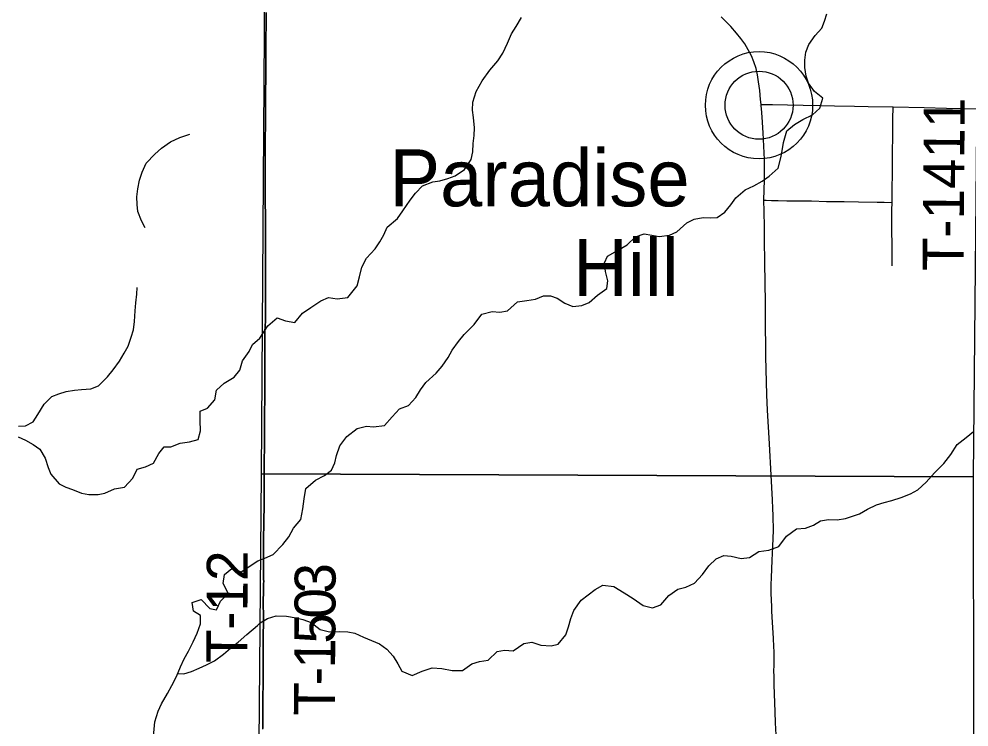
# Model space of a CAD drawing. Extents: x 0 to 70.2, y 0 to 31.4.
# Drawn here: x 6.434 to 7.753, y 14.97 to 15.952 of the extents above; entities that cross this region are included whole.
import ezdxf

# ---------------------------------------------------------------- set-up
doc = ezdxf.new("R2010")
doc.units = 0
for name, color, linetype in [('GM_X_County_Road', 7, 'Continuous'), ('GM_X_Minor_River', 7, 'Continuous'), ('GM_X_Section', 7, 'Continuous'), ('GM_X_Section_Text', 7, 'Continuous'), ('GM_X_State_Route', 7, 'Continuous'), ('GM_X_Township_Road', 7, 'Continuous'), ('GM_X_Township_Road_Text', 7, 'Continuous'), ('GM_X_Unincorporated', 7, 'Continuous'), ('GM_X_Unincorporated_Location', 7, 'Continuous'), ('GM_X_Unincorporated_Text', 7, 'Continuous'), ('SH_Cut_Line', 7, 'Continuous')]:
    doc.layers.add(name, color=color, linetype=linetype)

msp = doc.modelspace()

# ---------------------------------------------------------------- linework, layer by layer
at = {"layer": 'GM_X_County_Road'}
for points in [[(7.4642, 15.8337), (7.4797, 15.8335), (7.5009, 15.8332), (7.5227, 15.8328), (7.546, 15.8323), (7.5661, 15.8319), (7.5939, 15.8312), (7.6127, 15.8309), (7.6473, 15.8303)], [(7.6473, 15.8303), (7.6903, 15.8292), (7.7214, 15.8286), (7.7679, 15.8277), (7.8052, 15.8268), (7.917, 15.8247), (7.9789, 15.8235), (8.041, 15.8223), (8.0691, 15.822), (8.1468, 15.8216), (8.1996, 15.8212), (8.2617, 15.8195), (8.2673, 15.8194)]]:
    msp.add_lwpolyline(points, dxfattribs=at)
at = {"layer": 'GM_X_Minor_River'}
for points in [[(6.7657, 15.2005), (6.7754, 15.2041), (6.787, 15.2093), (6.8003, 15.2233), (6.8084, 15.2337), (6.8153, 15.2456), (6.8253, 15.258), (6.828, 15.2725), (6.8299, 15.2866), (6.8322, 15.301), (6.8456, 15.3124), (6.858, 15.3187), (6.8677, 15.3262), (6.8723, 15.3365), (6.8748, 15.3465), (6.8794, 15.3598), (6.8893, 15.373), (6.9035, 15.3839), (6.9166, 15.3873), (6.9261, 15.3864), (6.9412, 15.3883), (6.952, 15.4003), (6.9623, 15.4115), (6.9747, 15.416), (6.9847, 15.4272), (6.9912, 15.4376), (6.9986, 15.4481), (7.0131, 15.4609), (7.0212, 15.4706), (7.0296, 15.4826), (7.0351, 15.4926), (7.0439, 15.5049), (7.052, 15.5146), (7.0657, 15.5282), (7.0767, 15.5425), (7.0906, 15.5466), (7.1013, 15.5454), (7.1122, 15.5475), (7.126, 15.5596), (7.1388, 15.5618), (7.1509, 15.5636), (7.1621, 15.5681), (7.1716, 15.5679), (7.1812, 15.5651), (7.1919, 15.5578), (7.2027, 15.5531), (7.2155, 15.5545), (7.2253, 15.5589), (7.2368, 15.5691), (7.2502, 15.5781), (7.2515, 15.5888), (7.2481, 15.602), (7.2467, 15.6137), (7.251, 15.6233), (7.2649, 15.6312), (7.278, 15.6391), (7.2898, 15.65), (7.3019, 15.6541), (7.3125, 15.6521), (7.3224, 15.6504), (7.3371, 15.6523), (7.3473, 15.6571), (7.361, 15.6692), (7.3711, 15.6747), (7.3839, 15.6766), (7.3934, 15.6764), (7.4033, 15.6766), (7.4137, 15.6841), (7.4222, 15.6942), (7.4291, 15.7042), (7.4421, 15.7151), (7.4541, 15.7207), (7.4657, 15.7271), (7.4754, 15.7341), (7.488, 15.7454), (7.4915, 15.7596), (7.4932, 15.7691), (7.4952, 15.7809), (7.4997, 15.7969), (7.5105, 15.8059), (7.5221, 15.8127), (7.5356, 15.8194), (7.5456, 15.8284), (7.5498, 15.8425), (7.5383, 15.8517), (7.53, 15.8633), (7.5268, 15.8731), (7.525, 15.8848), (7.5247, 15.8951), (7.5264, 15.9061), (7.5303, 15.9168), (7.5391, 15.9292), (7.5483, 15.9393), (7.5523, 15.9492), (7.5551, 15.9595)], [(6.7682, 15.5096), (6.7793, 15.5263), (6.7923, 15.5376), (6.8041, 15.5334), (6.8171, 15.531), (6.8277, 15.5442), (6.8393, 15.552), (6.8531, 15.5611), (6.8636, 15.5659), (6.8758, 15.5639), (6.8905, 15.5658), (6.9034, 15.582), (6.9065, 15.5946), (6.91, 15.608), (6.9162, 15.6203), (6.9283, 15.6335), (6.9349, 15.6431), (6.9404, 15.6527), (6.9451, 15.6635), (6.9596, 15.6756), (6.9669, 15.686), (6.9768, 15.7007), (6.9842, 15.7107), (6.9941, 15.7208), (7.0084, 15.7261), (7.0182, 15.7278), (7.0295, 15.7307), (7.0393, 15.7348), (7.0524, 15.7434), (7.0615, 15.7573), (7.0639, 15.768), (7.0644, 15.7794), (7.066, 15.7904), (7.0665, 15.8011), (7.0647, 15.8155), (7.0637, 15.8257), (7.0642, 15.8367), (7.0688, 15.8516), (7.0768, 15.8666), (7.0878, 15.8813), (7.0985, 15.894), (7.1058, 15.9048), (7.1123, 15.9187), (7.1177, 15.9317), (7.1239, 15.9417), (7.1316, 15.9544)], [(6.6092, 15.6625), (6.6039, 15.6723), (6.599, 15.6852), (6.5982, 15.6947), (6.5978, 15.7053), (6.599, 15.7167), (6.6013, 15.7285), (6.6051, 15.7395), (6.6108, 15.752), (6.6225, 15.7645), (6.632, 15.7732), (6.6445, 15.782), (6.6574, 15.788), (6.6711, 15.7922)], [(6.4332, 15.3875), (6.443, 15.3878), (6.4536, 15.3935), (6.4601, 15.4034), (6.4688, 15.4178), (6.4798, 15.4284), (6.4893, 15.4322), (6.4995, 15.4353), (6.5113, 15.4372), (6.5207, 15.4383), (6.534, 15.4391), (6.5443, 15.4432), (6.5568, 15.4557), (6.5647, 15.4656), (6.5735, 15.4777), (6.5799, 15.4884), (6.5856, 15.4982), (6.5898, 15.5107), (6.5928, 15.521), (6.5943, 15.5327), (6.5955, 15.5472), (6.5963, 15.5582), (6.5974, 15.5703), (6.5982, 15.5798)], [(6.4331, 15.3723), (6.443, 15.3681), (6.4536, 15.362), (6.4631, 15.3556), (6.4703, 15.3431), (6.4744, 15.3302), (6.4782, 15.3207), (6.4896, 15.3074), (6.4991, 15.3025), (6.5085, 15.2995), (6.5207, 15.2945), (6.5309, 15.2926), (6.5438, 15.2926), (6.5533, 15.2945), (6.5665, 15.3002), (6.5806, 15.3025), (6.5923, 15.315), (6.598, 15.3275), (6.6098, 15.331), (6.6208, 15.3359), (6.628, 15.3492), (6.6356, 15.3587), (6.645, 15.3587), (6.6579, 15.3636), (6.6708, 15.3655), (6.6826, 15.3689), (6.686, 15.3807), (6.6856, 15.3951), (6.6853, 15.408), (6.6955, 15.4125), (6.7061, 15.4239), (6.708, 15.4372), (6.719, 15.447), (6.7327, 15.4554), (6.7406, 15.4652), (6.7444, 15.4781), (6.7535, 15.4907), (6.7581, 15.5005), (6.7682, 15.5096)], [(6.765, 15.1106), (6.7687, 15.1147), (6.7792, 15.1203), (6.7909, 15.124), (6.8053, 15.1236), (6.8186, 15.1216), (6.8281, 15.1192), (6.8396, 15.1149), (6.8523, 15.1053), (6.8649, 15.1018), (6.8789, 15.1025), (6.8903, 15.1021), (6.9002, 15.1), (6.9124, 15.0946), (6.9235, 15.0899), (6.9346, 15.0853), (6.9447, 15.0779), (6.9536, 15.0683), (6.9599, 15.0578), (6.9655, 15.0473), (6.9796, 15.0416), (6.9935, 15.0472), (7.0074, 15.0521), (7.0211, 15.0513), (7.0355, 15.0482), (7.0495, 15.0485), (7.0626, 15.0576), (7.0731, 15.0609), (7.0852, 15.0627), (7.0978, 15.0747), (7.108, 15.0765), (7.1201, 15.0756), (7.1347, 15.0859), (7.146, 15.0876), (7.1582, 15.0834), (7.1727, 15.0826), (7.1824, 15.0851), (7.1931, 15.0979), (7.1967, 15.109), (7.2002, 15.1204), (7.2041, 15.1315), (7.2144, 15.1458), (7.2337, 15.1607), (7.2442, 15.1666), (7.2598, 15.1651), (7.274, 15.156), (7.2867, 15.1483), (7.3002, 15.1384), (7.3135, 15.1353), (7.3248, 15.1393), (7.3362, 15.1525), (7.3485, 15.1611), (7.3598, 15.1641), (7.3718, 15.1697), (7.3829, 15.1813), (7.3914, 15.1937), (7.4017, 15.2034), (7.4122, 15.2078), (7.4225, 15.2069), (7.4366, 15.2035), (7.4479, 15.2052), (7.461, 15.2135), (7.4746, 15.2154), (7.4885, 15.2202), (7.4992, 15.2345), (7.5133, 15.2447), (7.5258, 15.2458), (7.5367, 15.2499), (7.5464, 15.2558), (7.5577, 15.2576), (7.5695, 15.2575), (7.5812, 15.2593), (7.6007, 15.2658), (7.6116, 15.2721), (7.6243, 15.2781), (7.6349, 15.2814), (7.6454, 15.2843), (7.6586, 15.2884), (7.6713, 15.2933), (7.6814, 15.2992), (7.6933, 15.3097), (7.7048, 15.3225), (7.7177, 15.3354), (7.7276, 15.3481), (7.7364, 15.362), (7.7487, 15.3718), (7.7587, 15.38)], [(6.6206, 14.957), (6.6225, 14.9771), (6.6274, 14.9919), (6.632, 15.0021), (6.6403, 15.0165), (6.6464, 15.0275), (6.6525, 15.04), (6.6582, 15.0533), (6.6635, 15.0643), (6.6695, 15.0753), (6.6756, 15.0882), (6.6813, 15.1), (6.6859, 15.1129), (6.6862, 15.1246), (6.6764, 15.1307), (6.6745, 15.1428), (6.687, 15.147), (6.6988, 15.1345), (6.7082, 15.1326), (6.7139, 15.1447), (6.7242, 15.1557), (6.7173, 15.169), (6.7193, 15.1815), (6.7295, 15.1899), (6.7424, 15.1853), (6.7657, 15.2005)], [(6.6543, 15.0443), (6.6627, 15.0435), (6.6737, 15.0469), (6.6843, 15.0518), (6.6945, 15.0564), (6.7052, 15.0617), (6.7181, 15.0712), (6.7275, 15.0795), (6.7382, 15.0878), (6.7503, 15.0981), (6.765, 15.1106)]]:
    msp.add_lwpolyline(points, dxfattribs=at)
at = {"layer": 'GM_X_Section'}
for points in [[(6.7778, 16.3386), (7.7683, 16.3298), (7.7584, 15.3168), (6.7706, 15.321)], [(6.7706, 15.321), (7.7584, 15.3168), (7.7596, 14.2988), (6.7617, 14.3072)]]:
    msp.add_lwpolyline(points, close=True, dxfattribs=at)
at = {"layer": 'GM_X_Section_Text'}
for points in [[(6.7771, 15.9614), (6.7769, 15.9086), (6.7768, 15.8931), (6.7765, 15.8683), (6.7763, 15.8528), (6.7762, 15.8188), (6.7758, 15.7723), (6.7757, 15.7506), (6.7759, 15.7165), (6.7761, 15.6606), (6.776, 15.6419), (6.7762, 15.5829), (6.7763, 15.5707), (6.7763, 15.5487), (6.7761, 15.5336), (6.7755, 15.5187), (6.7754, 15.5055), (6.7754, 15.4901), (6.7752, 15.4713), (6.7753, 15.4495), (6.7752, 15.4247), (6.7749, 15.4062), (6.7746, 15.3596), (6.7745, 15.3381), (6.7743, 15.3099), (6.7742, 15.2818), (6.7737, 15.2508), (6.7735, 15.2322), (6.7735, 15.226), (6.7736, 15.2198), (6.7736, 15.1998), (6.7736, 15.1926), (6.7736, 15.1834), (6.7736, 15.1793), (6.7736, 15.1751), (6.7737, 15.1719), (6.7736, 15.169), (6.7735, 15.1661), (6.7733, 15.1573), (6.7731, 15.145), (6.7734, 15.12), (6.7732, 15.092), (6.773, 15.0547), (6.7728, 15.0329), (6.7726, 15.0081), (6.7725, 14.9863), (6.7723, 14.9677)], [(6.7723, 14.9677), (6.7725, 14.9863), (6.7726, 15.0081), (6.7728, 15.0329), (6.773, 15.0547), (6.7732, 15.092), (6.7734, 15.12), (6.7731, 15.145), (6.7733, 15.1573), (6.7735, 15.1661), (6.7736, 15.169), (6.7737, 15.1719), (6.7736, 15.1751), (6.7736, 15.1793), (6.7736, 15.1834), (6.7736, 15.1926), (6.7736, 15.1998), (6.7736, 15.2198), (6.7735, 15.226), (6.7735, 15.2322), (6.7737, 15.2508), (6.7742, 15.2818), (6.7743, 15.3099), (6.7745, 15.3381), (6.7746, 15.3596), (6.7749, 15.4062), (6.7752, 15.4247), (6.7753, 15.4495), (6.7752, 15.4713), (6.7754, 15.4901), (6.7754, 15.5055), (6.7755, 15.5187), (6.7761, 15.5336), (6.7763, 15.5487), (6.7763, 15.5707), (6.7762, 15.5829), (6.776, 15.6419), (6.7761, 15.6606), (6.7759, 15.7165), (6.7757, 15.7506), (6.7758, 15.7723), (6.7762, 15.8188), (6.7763, 15.8528), (6.7765, 15.8683), (6.7768, 15.8931), (6.7769, 15.9086), (6.7771, 15.9614)]]:
    msp.add_lwpolyline(points, dxfattribs=at)
at = {"layer": 'GM_X_State_Route'}
msp.add_lwpolyline([(7.4856, 14.9508), (7.4841, 14.9756), (7.4834, 14.9911), (7.4823, 15.0284), (7.482, 15.0408), (7.4819, 15.047), (7.4821, 15.0562), (7.4822, 15.0593), (7.4823, 15.0624), (7.4821, 15.0748), (7.4818, 15.081), (7.4814, 15.0934), (7.48, 15.1151), (7.4792, 15.1306), (7.4788, 15.1399), (7.4787, 15.143), (7.4781, 15.1584), (7.4782, 15.1675), (7.4784, 15.1767), (7.4796, 15.2015), (7.4805, 15.2201), (7.481, 15.2325), (7.4811, 15.2419), (7.4808, 15.2636), (7.4805, 15.2729), (7.4801, 15.2853), (7.4781, 15.3194), (7.4758, 15.3628), (7.4732, 15.4093), (7.4721, 15.431), (7.4708, 15.4838), (7.4701, 15.5397), (7.47, 15.5584), (7.4691, 15.6143), (7.469, 15.6458), (7.4686, 15.6638), (7.4685, 15.6853), (7.4681, 15.7007), (7.4687, 15.729), (7.4689, 15.7415), (7.4687, 15.7571), (7.4681, 15.7757), (7.4671, 15.7942), (7.4657, 15.8159), (7.4647, 15.8282), (7.4644, 15.8313), (7.4642, 15.8337), (7.4634, 15.8405), (7.4622, 15.8528), (7.4607, 15.8652), (7.4592, 15.8745), (7.4571, 15.8836), (7.4542, 15.8926), (7.4506, 15.9012), (7.4463, 15.9096), (7.4414, 15.9176), (7.436, 15.9253), (7.4301, 15.9326), (7.4219, 15.9419), (7.4088, 15.9553)], dxfattribs=at)
at = {"layer": 'GM_X_Township_Road'}
for points in [[(6.7725, 14.9671), (6.7727, 14.9858), (6.7728, 15.0075), (6.773, 15.0324), (6.7732, 15.0541), (6.7734, 15.0915), (6.7736, 15.1194), (6.7734, 15.1445), (6.7735, 15.1567), (6.7737, 15.1656), (6.7738, 15.1684), (6.7739, 15.1714), (6.7739, 15.1745), (6.7739, 15.1788), (6.7739, 15.1828), (6.7738, 15.1921), (6.7738, 15.1993), (6.7738, 15.2192), (6.7737, 15.2254), (6.7737, 15.2316), (6.7739, 15.2502), (6.7744, 15.2813), (6.7745, 15.3094), (6.7747, 15.3376), (6.7748, 15.3591), (6.7751, 15.4057), (6.7754, 15.4241), (6.7755, 15.449), (6.7755, 15.4707), (6.7756, 15.4895), (6.7756, 15.5049), (6.7757, 15.5182), (6.7763, 15.533), (6.7766, 15.5482), (6.7766, 15.5702), (6.7764, 15.5824), (6.7762, 15.6414), (6.7764, 15.66), (6.7761, 15.7159), (6.7759, 15.7501), (6.776, 15.7718), (6.7764, 15.8182), (6.7765, 15.8522), (6.7767, 15.8677), (6.7771, 15.8925), (6.7771, 15.9081), (6.7773, 15.9609)], [(7.6459, 15.6977), (7.6461, 15.7044), (7.6461, 15.7133), (7.6463, 15.7409), (7.6466, 15.7691), (7.6467, 15.7879), (7.6468, 15.8004), (7.6471, 15.816), (7.6473, 15.8276), (7.6473, 15.8303)], [(7.4681, 15.7007), (7.4713, 15.7007), (7.4786, 15.7006), (7.4879, 15.7006), (7.5, 15.7001), (7.5187, 15.6998), (7.5341, 15.6997), (7.5548, 15.6992), (7.5794, 15.6988), (7.5994, 15.6985), (7.6254, 15.6982), (7.6351, 15.6979), (7.6459, 15.6977)], [(7.6462, 15.6096), (7.6459, 15.6378), (7.6456, 15.6597), (7.6455, 15.6722), (7.6457, 15.687), (7.6459, 15.6977)]]:
    msp.add_lwpolyline(points, dxfattribs=at)
at = {"layer": 'GM_X_Unincorporated'}
for radius in [0.0744, 0.0472]:
    msp.add_circle((7.4612, 15.8326), radius, dxfattribs=at)
at = {"layer": 'GM_X_Unincorporated_Location'}
msp.add_line((7.4612, 15.8326), (7.4612, 15.8326), dxfattribs=at)
at = {"layer": 'SH_Cut_Line'}
for points in [[(6.7723, 14.9677), (6.7725, 14.9863), (6.7726, 15.0081), (6.7728, 15.0329), (6.773, 15.0547), (6.7732, 15.092), (6.7734, 15.12), (6.7731, 15.145), (6.7733, 15.1573), (6.7735, 15.1661), (6.7736, 15.169), (6.7737, 15.1719), (6.7736, 15.1751), (6.7736, 15.1793), (6.7736, 15.1834), (6.7736, 15.1926), (6.7736, 15.1998), (6.7736, 15.2198), (6.7735, 15.226), (6.7735, 15.2322), (6.7737, 15.2508), (6.7742, 15.2818), (6.7743, 15.3099), (6.7745, 15.3381), (6.7746, 15.3596), (6.7749, 15.4062), (6.7752, 15.4247), (6.7753, 15.4495), (6.7752, 15.4713), (6.7754, 15.4901), (6.7754, 15.5055), (6.7755, 15.5187), (6.7761, 15.5336), (6.7763, 15.5487), (6.7763, 15.5707), (6.7762, 15.5829), (6.776, 15.6419), (6.7761, 15.6606), (6.7759, 15.7165), (6.7757, 15.7506), (6.7758, 15.7723), (6.7762, 15.8188), (6.7763, 15.8528), (6.7765, 15.8683), (6.7768, 15.8931), (6.7769, 15.9086), (6.7771, 15.9614)], [(6.7771, 15.9614), (6.7769, 15.9086), (6.7768, 15.8931), (6.7765, 15.8683), (6.7763, 15.8528), (6.7762, 15.8188), (6.7758, 15.7723), (6.7757, 15.7506), (6.7759, 15.7165), (6.7761, 15.6606), (6.776, 15.6419), (6.7762, 15.5829), (6.7763, 15.5707), (6.7763, 15.5487), (6.7761, 15.5336), (6.7755, 15.5187), (6.7754, 15.5055), (6.7754, 15.4901), (6.7752, 15.4713), (6.7753, 15.4495), (6.7752, 15.4247), (6.7749, 15.4062), (6.7746, 15.3596), (6.7745, 15.3381), (6.7743, 15.3099), (6.7742, 15.2818), (6.7737, 15.2508), (6.7735, 15.2322), (6.7735, 15.226), (6.7736, 15.2198), (6.7736, 15.1998), (6.7736, 15.1926), (6.7736, 15.1834), (6.7736, 15.1793), (6.7736, 15.1751), (6.7737, 15.1719), (6.7736, 15.169), (6.7735, 15.1661), (6.7733, 15.1573), (6.7731, 15.145), (6.7734, 15.12), (6.7732, 15.092), (6.773, 15.0547), (6.7728, 15.0329), (6.7726, 15.0081), (6.7725, 14.9863), (6.7723, 14.9677)]]:
    msp.add_lwpolyline(points, dxfattribs=at)

# ---------------------------------------------------------------- texts
at = {"layer": 'GM_X_Township_Road_Text'}
for s, height, rotation, p in [('T-1411', 0.05682, 89.558, (7.745, 15.6022)), ('T-12', 0.05682, 89.6355, (6.7507, 15.0584)), ('3', 0.0568, 89.6409, (6.8734, 15.155)), ('0', 0.0568, 89.6381, (6.8732, 15.1203)), ('5', 0.0568, 89.6356, (6.873, 15.0856)), ('1', 0.0568, 89.6346, (6.8728, 15.0509)), ('-', 0.0568, 89.6268, (6.8726, 15.0277)), ('T', 0.0568, 89.5889, (6.8723, 14.9853))]:
    msp.add_text(s, height=height, rotation=rotation, dxfattribs=at).set_placement(p)
at = {"layer": 'GM_X_Unincorporated_Text'}
for s, p in [('Paradise', (6.9481, 15.6923)), ('Hill', (7.2031, 15.5681))]:
    msp.add_text(s, height=0.07898, rotation=0, dxfattribs=at).set_placement(p)

doc.saveas('drawing.dxf')
